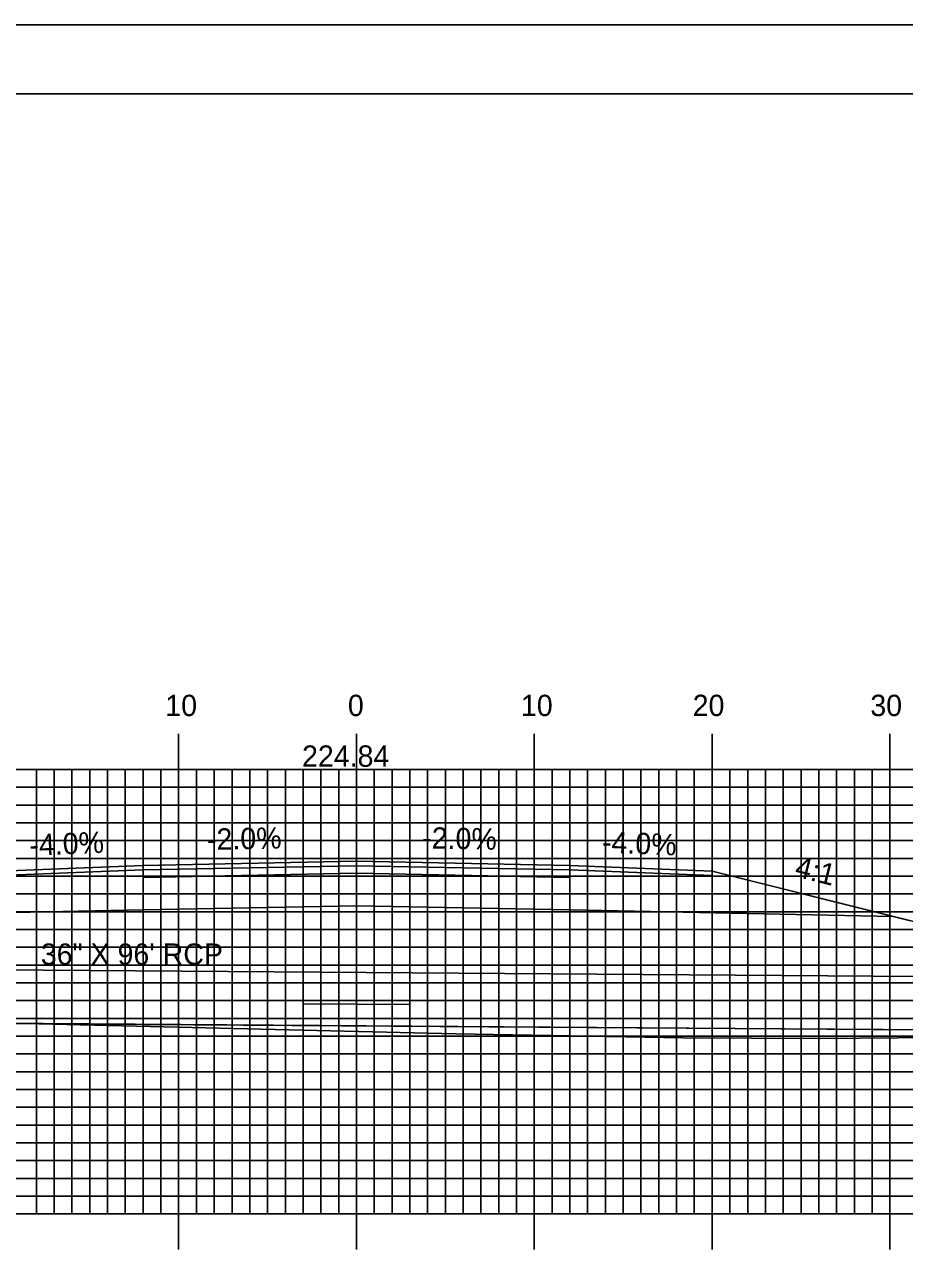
# Model space of a CAD drawing. Extents: x 1819244 to 1819587, y 442591 to 442811.
# Drawn here: x 1819391 to 1819440.5, y 442741.2 to 442810.5 of the extents above; entities that cross this region are included whole.
import ezdxf

# ---------------------------------------------------------------- set-up
doc = ezdxf.new("R2010")
doc.units = 0
for name, color, linetype in [('ANNOTATION', 7, 'Continuous'), ('BORDER', 7, 'Continuous'), ('D_Drainage_Culvert', 7, 'Continuous'), ('D_Drainage_Text', 7, 'Continuous'), ('D_Roadway_Centerline', 7, 'Continuous'), ('D_Roadway_Centerline_Text', 7, 'Continuous'), ('D_Roadway_Edge_Shoulder', 7, 'Continuous'), ('D_Roadway_Edge_TW', 7, 'Continuous'), ('D_Roadway_Pavement', 7, 'Continuous'), ('D_Roadway_SlopeLines', 7, 'Continuous'), ('D_Roadway_SubGrade', 7, 'Continuous'), ('H_V ANNOTATION', 7, 'Continuous'), ('MAJOR', 7, 'Continuous'), ('MINOR', 7, 'Continuous'), ('PLOT BOUNDARY', 7, 'Continuous'), ('S_Roadway_Centerline', 7, 'Continuous')]:
    doc.layers.add(name, color=color, linetype=linetype)

msp = doc.modelspace()

# ---------------------------------------------------------------- linework, layer by layer
at = {"layer": 'BORDER'}
msp.add_lwpolyline([(1819260.065, 442596.665), (1819580.065, 442596.665), (1819580.065, 442806.665), (1819260.065, 442806.665)], close=True, dxfattribs=at)
at = {"layer": 'D_Drainage_Culvert'}
for p, q in [((1819406.665, 442755.487), (1819412.665, 442755.445)), ((1819364.881, 442754.558), (1819456.879, 442753.917))]:
    msp.add_line(p, q, dxfattribs=at)
msp.add_lwpolyline([(1819360.881, 442754.596), (1819360.902, 442757.596), (1819456.9, 442756.917), (1819456.879, 442753.917)], close=True, dxfattribs=at)
at = {"layer": 'D_Roadway_Centerline'}
msp.add_lwpolyline([(1819373.094, 442758.418), (1819377.665, 442759.942), (1819379.491, 442760.398), (1819389.665, 442762.942), (1819397.665, 442763.262), (1819409.665, 442763.502), (1819421.665, 442763.262), (1819429.665, 442762.942), (1819439.839, 442760.398), (1819441.665, 442759.942), (1819448.263, 442757.86)], dxfattribs=at)
at = {"layer": 'D_Roadway_Edge_Shoulder'}
for points in [[(1819397.665, 442763.262), (1819389.665, 442762.942), (1819389.665, 442762.692), (1819397.665, 442763.012)], [(1819421.665, 442763.262), (1819429.665, 442762.942), (1819429.665, 442762.692), (1819421.665, 442763.012)]]:
    msp.add_lwpolyline(points, close=True, dxfattribs=at)
at = {"layer": 'D_Roadway_Edge_TW'}
msp.add_lwpolyline([(1819397.665, 442763.012), (1819397.665, 442763.262), (1819409.665, 442763.502), (1819421.665, 442763.262), (1819421.665, 442763.012), (1819409.665, 442763.252)], close=True, dxfattribs=at)
at = {"layer": 'D_Roadway_Pavement'}
msp.add_lwpolyline([(1819397.665, 442762.595), (1819397.665, 442763.012), (1819409.665, 442763.252), (1819421.665, 442763.012), (1819421.665, 442762.595), (1819409.665, 442762.835)], close=True, dxfattribs=at)
at = {"layer": 'D_Roadway_SlopeLines'}
msp.add_lwpolyline([(1819429.665, 442762.942), (1819441.665, 442759.942), (1819448.263, 442757.86)], dxfattribs=at)
at = {"layer": 'D_Roadway_SubGrade'}
msp.add_lwpolyline([(1819397.665, 442760.762), (1819379.491, 442760.398), (1819389.665, 442762.942), (1819389.665, 442762.692), (1819397.665, 442763.012), (1819409.665, 442763.252), (1819421.665, 442763.012), (1819429.665, 442762.692), (1819429.665, 442762.942), (1819439.839, 442760.398), (1819421.665, 442760.762), (1819409.665, 442761.002)], close=True, dxfattribs=at)
at = {"layer": 'MAJOR'}
for p, q in [((1819399.665, 442770.669), (1819399.665, 442768.665)), ((1819409.665, 442770.669), (1819409.665, 442768.665)), ((1819419.665, 442770.669), (1819419.665, 442768.665)), ((1819429.665, 442770.669), (1819429.665, 442768.665)), ((1819439.665, 442770.669), (1819439.665, 442768.665)), ((1819269.665, 442768.665), (1819549.665, 442768.665)), ((1819269.665, 442768.665), (1819549.665, 442768.665)), ((1819399.665, 442743.665), (1819399.665, 442768.665)), ((1819409.665, 442743.665), (1819409.665, 442768.665)), ((1819419.665, 442743.665), (1819419.665, 442768.665)), ((1819429.665, 442743.665), (1819429.665, 442768.665)), ((1819439.665, 442743.665), (1819439.665, 442768.665)), ((1819269.665, 442763.665), (1819549.665, 442763.665)), ((1819269.665, 442758.665), (1819549.665, 442758.665)), ((1819269.665, 442753.665), (1819549.665, 442753.665)), ((1819269.665, 442748.665), (1819549.665, 442748.665)), ((1819269.665, 442743.665), (1819549.665, 442743.665)), ((1819269.665, 442743.665), (1819549.665, 442743.665)), ((1819399.665, 442741.661), (1819399.665, 442743.665)), ((1819409.665, 442741.661), (1819409.665, 442743.665)), ((1819419.665, 442741.661), (1819419.665, 442743.665)), ((1819429.665, 442741.661), (1819429.665, 442743.665)), ((1819439.665, 442741.661), (1819439.665, 442743.665))]:
    msp.add_line(p, q, dxfattribs=at)
at = {"layer": 'MINOR'}
for p, q in [((1819391.665, 442743.665), (1819391.665, 442768.665)), ((1819392.665, 442743.665), (1819392.665, 442768.665)), ((1819393.665, 442743.665), (1819393.665, 442768.665)), ((1819394.665, 442743.665), (1819394.665, 442768.665)), ((1819395.665, 442743.665), (1819395.665, 442768.665)), ((1819396.665, 442743.665), (1819396.665, 442768.665)), ((1819397.665, 442743.665), (1819397.665, 442768.665)), ((1819398.665, 442743.665), (1819398.665, 442768.665)), ((1819400.665, 442743.665), (1819400.665, 442768.665)), ((1819401.665, 442743.665), (1819401.665, 442768.665)), ((1819402.665, 442743.665), (1819402.665, 442768.665)), ((1819403.665, 442743.665), (1819403.665, 442768.665)), ((1819404.665, 442743.665), (1819404.665, 442768.665)), ((1819405.665, 442743.665), (1819405.665, 442768.665)), ((1819406.665, 442743.665), (1819406.665, 442768.665)), ((1819407.665, 442743.665), (1819407.665, 442768.665)), ((1819408.665, 442743.665), (1819408.665, 442768.665)), ((1819410.665, 442743.665), (1819410.665, 442768.665)), ((1819411.665, 442743.665), (1819411.665, 442768.665)), ((1819412.665, 442743.665), (1819412.665, 442768.665)), ((1819413.665, 442743.665), (1819413.665, 442768.665)), ((1819414.665, 442743.665), (1819414.665, 442768.665)), ((1819415.665, 442743.665), (1819415.665, 442768.665)), ((1819416.665, 442743.665), (1819416.665, 442768.665)), ((1819417.665, 442743.665), (1819417.665, 442768.665)), ((1819418.665, 442743.665), (1819418.665, 442768.665)), ((1819420.665, 442743.665), (1819420.665, 442768.665)), ((1819421.665, 442743.665), (1819421.665, 442768.665)), ((1819422.665, 442743.665), (1819422.665, 442768.665)), ((1819423.665, 442743.665), (1819423.665, 442768.665)), ((1819424.665, 442743.665), (1819424.665, 442768.665)), ((1819425.665, 442743.665), (1819425.665, 442768.665)), ((1819426.665, 442743.665), (1819426.665, 442768.665)), ((1819427.665, 442743.665), (1819427.665, 442768.665)), ((1819428.665, 442743.665), (1819428.665, 442768.665)), ((1819430.665, 442743.665), (1819430.665, 442768.665)), ((1819431.665, 442743.665), (1819431.665, 442768.665)), ((1819432.665, 442743.665), (1819432.665, 442768.665)), ((1819433.665, 442743.665), (1819433.665, 442768.665)), ((1819434.665, 442743.665), (1819434.665, 442768.665)), ((1819435.665, 442743.665), (1819435.665, 442768.665)), ((1819436.665, 442743.665), (1819436.665, 442768.665)), ((1819437.665, 442743.665), (1819437.665, 442768.665)), ((1819438.665, 442743.665), (1819438.665, 442768.665)), ((1819269.665, 442767.665), (1819549.665, 442767.665)), ((1819269.665, 442766.665), (1819549.665, 442766.665)), ((1819269.665, 442765.665), (1819549.665, 442765.665)), ((1819269.665, 442764.665), (1819549.665, 442764.665)), ((1819269.665, 442762.665), (1819549.665, 442762.665)), ((1819269.665, 442761.665), (1819549.665, 442761.665)), ((1819269.665, 442760.665), (1819549.665, 442760.665)), ((1819269.665, 442759.665), (1819549.665, 442759.665)), ((1819269.665, 442757.665), (1819549.665, 442757.665)), ((1819269.665, 442756.665), (1819549.665, 442756.665)), ((1819269.665, 442755.665), (1819549.665, 442755.665)), ((1819269.665, 442754.665), (1819549.665, 442754.665)), ((1819269.665, 442752.665), (1819549.665, 442752.665)), ((1819269.665, 442751.665), (1819549.665, 442751.665)), ((1819269.665, 442750.665), (1819549.665, 442750.665)), ((1819269.665, 442749.665), (1819549.665, 442749.665)), ((1819269.665, 442747.665), (1819549.665, 442747.665)), ((1819269.665, 442746.665), (1819549.665, 442746.665)), ((1819269.665, 442745.665), (1819549.665, 442745.665)), ((1819269.665, 442744.665), (1819549.665, 442744.665))]:
    msp.add_line(p, q, dxfattribs=at)
at = {"layer": 'PLOT BOUNDARY'}
msp.add_lwpolyline([(1819243.878, 442590.547), (1819583.878, 442590.547), (1819583.878, 442810.547), (1819243.878, 442810.547)], close=True, dxfattribs=at)
at = {"layer": 'S_Roadway_Centerline'}
msp.add_lwpolyline([(1819269.665, 442757.95), (1819272.752, 442757.702), (1819292.958, 442756.18), (1819302.01, 442755.845), (1819313.002, 442755.778), (1819320.093, 442755.729), (1819329.655, 442755.679), (1819340.464, 442755.086), (1819358.276, 442754.65), (1819368.644, 442754.436), (1819381.597, 442754.609), (1819381.856, 442754.609), (1819382.406, 442754.589), (1819415.248, 442753.801), (1819428.01, 442753.581), (1819435.779, 442753.54), (1819448.768, 442753.643), (1819449.398, 442753.657), (1819462.466, 442753.958), (1819468.069, 442753.858), (1819486.973, 442753.903)], dxfattribs=at)

# ---------------------------------------------------------------- texts
at = {"layer": 'ANNOTATION'}
for s, rotation, p in [('-4.0%', 2.29061, (1819391.296, 442763.809)), ('-2.0%', 1.14576, (1819401.271, 442764.134)), ('-2.0%', 358.85424, (1819413.351, 442764.228)), ('-4.0%', 357.70939, (1819423.456, 442763.992)), ('4:1', 345.96376, (1819434.257, 442762.655))]:
    msp.add_text(s, height=1.2, rotation=rotation, dxfattribs=at).set_placement(p)
at = {"layer": 'D_Drainage_Text'}
msp.add_text('36" X 96\' RCP', height=1.2, dxfattribs=at).set_placement((1819391.913, 442757.678))
at = {"layer": 'D_Roadway_Centerline'}
for s, p in [('C', (1819409.659, 442763.502)), ('L', (1819409.665, 442763.494))]:
    msp.add_text(s, height=0.0146, dxfattribs=at).set_placement(p)
at = {"layer": 'D_Roadway_Centerline_Text'}
msp.add_text('224.84', height=1.2, dxfattribs=at).set_placement((1819406.604, 442768.815))
at = {"layer": 'H_V ANNOTATION'}
for s, p in [('10', (1819398.915, 442771.665)), ('0', (1819409.183, 442771.665)), ('10', (1819418.915, 442771.665)), ('20', (1819428.573, 442771.665)), ('30', (1819438.562, 442771.665))]:
    msp.add_text(s, height=1.2, dxfattribs=at).set_placement(p)

doc.saveas('drawing.dxf')
